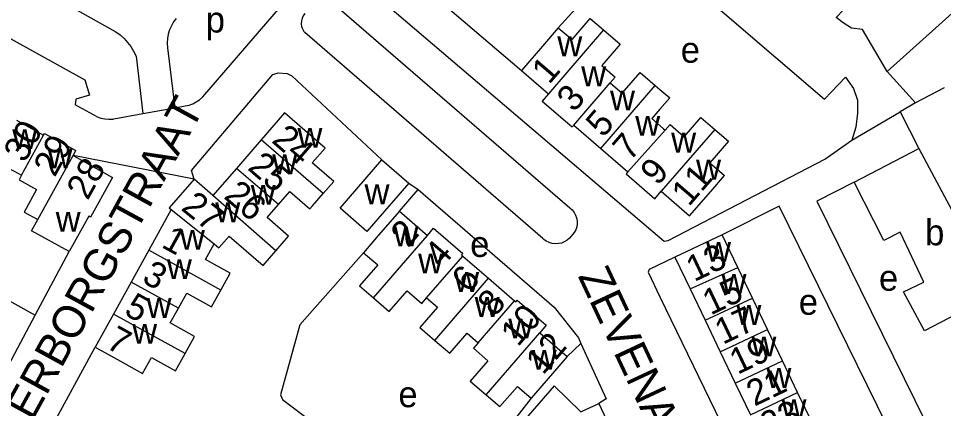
# Model space of a CAD drawing. Extents: x 158356 to 159894, y 383831 to 385260.
# Drawn here: x 159000.7 to 159143.9, y 384024.6 to 384085.1 of the extents above; entities that cross this region are included whole.
import ezdxf

# ---------------------------------------------------------------- set-up
doc = ezdxf.new("R2010")
doc.units = 0
for name, color, linetype in [('BLT_Basislijn', 7, 'Continuous'), ('BLT_Bebouwing', 7, 'Continuous'), ('BLT_Centroide', 7, 'Continuous'), ('BLT_Huisnummer', 7, 'Continuous'), ('BLT_Huisnummer_ tussenligend', 7, 'Continuous'), ('BLT_Onderverdeling_panden', 7, 'Continuous'), ('BLT_Straatnaam', 7, 'Continuous'), ('BLT_Vlakafsluiter', 7, 'Continuous')]:
    doc.layers.add(name, color=color, linetype=linetype)

msp = doc.modelspace()

# ---------------------------------------------------------------- linework, layer by layer
at = {"layer": 'BLT_Basislijn'}
for p, q in [((158953.11, 384118.31), (159015.76, 384083.03)), ((159084.24, 384083.64), (159096.05, 384096.73)), ((159049.22, 384087.62), (159086.05, 384055.72)), ((159029.22, 384072.94), (159041.26, 384086.88)), ((159067.13, 384086.81), (159078.55, 384077.03)), ((159081.89, 384050.97), (159045.03, 384082.9)), ((159023.77, 384080.55), (159024.88, 384071.25)), ((159018.89, 384079.24), (159019.95, 384070.35)), ((159012.87, 384069.86), (159009.45, 384071.71)), ((159139.58, 384072.02), (159137.17, 384070.6)), ((159015.45, 384069.52), (159019.95, 384070.35)), ((159019.95, 384070.35), (159024.88, 384071.25)), ((159024.88, 384071.25), (159026.5, 384071.54)), ((159129.68, 384066.25), (159137.17, 384070.6)), ((159137.17, 384070.6), (159140.09, 384064.94)), ((159061.1, 384059.58), (159062.57, 384058.61)), ((159059.66, 384055.21), (159062.57, 384058.61)), ((159086.53, 384051.68), (159085.98, 384051.03)), ((159003.29, 384039.1), (159008.56, 384048.99)), ((158991.32, 384045.7), (159003.29, 384039.1)), ((158996.15, 384025.71), (159003.29, 384039.1)), ((159087.75, 384034.74), (159085.65, 384032.72)), ((159005.27, 384020.8), (159012.56, 384034.13)), ((159080.04, 384026.23), (159070.07, 384013.46))]:
    msp.add_line(p, q, dxfattribs=at)
for points in [[(159069.13, 384107.67), (159068.01, 384107.77), (159066.54, 384106.24), (159054, 384091.81), (159053.62, 384090.73), (159100, 384051.15), (159100.67, 384050.58), (159101.28, 384050.68)], [(158971.07, 384097.59), (158986.45, 384089.14), (158987.15, 384086.76), (158985, 384086.14), (158984.88, 384085.24), (158989.31, 384082.78), (158990.81, 384082.66), (158995.65, 384084.07), (159010.99, 384075.6), (159011.7, 384073.19), (159009.56, 384072.58), (159009.45, 384071.71)], [(159102.52, 384092.35), (159125.48, 384072.6), (159128.71, 384076), (159129.94, 384074.26), (159130.56, 384072.41), (159130.56, 384070.43), (159130.33, 384068.23), (159129.68, 384066.25)], [(159135.19, 384076.87), (159131.34, 384083.38), (159129.67, 384083.6), (159128.37, 384084.4), (159127.3, 384085.24), (159130.84, 384089.01)], [(159025.12, 384085.11), (159024.71, 384084.55), (159024.37, 384083.95), (159024.09, 384083.31), (159023.89, 384082.65), (159023.77, 384081.97), (159023.73, 384081.28), (159023.77, 384080.55)], [(159045.02, 384085.86), (159044.77, 384085.51), (159044.6, 384085.13), (159044.49, 384084.72), (159044.47, 384084.29), (159044.53, 384083.87), (159044.66, 384083.47), (159044.87, 384083.1), (159045.03, 384082.9)], [(159015.76, 384083.03), (159016.42, 384082.55), (159017.03, 384082), (159017.59, 384081.39), (159018.08, 384080.74), (159018.51, 384080.04), (159018.89, 384079.24)], [(159027.88, 384060.18), (159027.5, 384061.52), (159040.06, 384076.43), (159040.88, 384076.66), (159042.3, 384076.59), (159042.99, 384076.22), (159056.95, 384063.17)], [(159026.5, 384071.54), (159027.1, 384071.67), (159027.68, 384071.87), (159028.22, 384072.15), (159028.73, 384072.49), (159029.22, 384072.94)], [(159012.87, 384069.86), (159013.45, 384069.65), (159014.06, 384069.52), (159014.68, 384069.47), (159015.31, 384069.5), (159015.45, 384069.52)], [(159101.28, 384050.68), (159125.52, 384063.28), (159129.68, 384066.25)], [(159130.07, 384059.7), (159124.27, 384056.8), (159146.23, 384012.21), (159163.28, 384020.54)], [(159062.57, 384058.61), (159083.6, 384040.35), (159087.4, 384035.6), (159087.75, 384034.74)], [(159131.86, 384005.09), (159141.23, 384009.67), (159118.45, 384056), (159109.62, 384051.58)], [(159086.05, 384055.72), (159086.41, 384055.41), (159086.71, 384055.04), (159086.94, 384054.63), (159087.1, 384054.19), (159087.18, 384053.73), (159087.18, 384053.26), (159087.11, 384052.79), (159086.95, 384052.35), (159086.73, 384051.94), (159086.53, 384051.68)], [(159085.98, 384051.03), (159085.61, 384050.71), (159085.19, 384050.47), (159084.74, 384050.29), (159084.27, 384050.19), (159083.78, 384050.17), (159083.3, 384050.23), (159082.84, 384050.37), (159082.4, 384050.58), (159082.01, 384050.86), (159081.89, 384050.97)], [(159054.11, 384048.78), (159044.27, 384037.62), (159041.24, 384026.76), (159041.56, 384026.03), (159046.04, 384022.62), (159046.67, 384022.22)], [(159102.32, 384048.1), (159098.34, 384046.21), (159098.18, 384045.79), (159100, 384041.97), (159120.53, 383999.56)], [(159087.75, 384034.74), (159091.65, 384026.12), (159090.52, 384025.43)]]:
    msp.add_lwpolyline(points, dxfattribs=at)
at = {"layer": 'BLT_Bebouwing'}
for p, q in [((159078.55, 384077.03), (159082.74, 384073.42)), ((159139.58, 384072.02), (159135.19, 384076.87)), ((159143.99, 384074.36), (159139.58, 384072.02)), ((159000.38, 384069.33), (159004.58, 384067.01)), ((159086.65, 384068.58), (159090.85, 384064.95)), ((159004.58, 384067.01), (159004.73, 384067.28)), ((159004.73, 384067.28), (159009.57, 384064.61)), ((159038.24, 384066.28), (159034.43, 384061.86)), ((159009.14, 384063.83), (159009.57, 384064.61)), ((159090.85, 384064.95), (159095.05, 384061.33)), ((159130.07, 384059.7), (159140.09, 384064.94)), ((159140.09, 384064.94), (159152.02, 384042.49)), ((159056.95, 384063.17), (159061.1, 384059.58)), ((159034.43, 384061.86), (159030.79, 384057.66)), ((159030.79, 384057.66), (159027.88, 384060.18)), ((159100.18, 384058.31), (159104.59, 384054.51)), ((159024.34, 384055.49), (159020.85, 384049.16)), ((159059.66, 384055.21), (159064, 384051.47)), ((159109.62, 384051.58), (159102.32, 384048.1)), ((159112.04, 384046.52), (159109.62, 384051.58)), ((159020.85, 384049.16), (159018.14, 384044.24)), ((159069.47, 384048.27), (159073.46, 384044.82)), ((159102.32, 384048.1), (159104.66, 384043.2)), ((159114.33, 384041.74), (159112.04, 384046.52)), ((159073.46, 384044.82), (159077.47, 384041.35)), ((159018.14, 384044.24), (159015.4, 384039.28)), ((159104.66, 384043.2), (159107, 384038.31)), ((159116.65, 384036.88), (159114.33, 384041.74)), ((159015.4, 384039.28), (159012.56, 384034.13)), ((159107, 384038.31), (159109.33, 384033.44)), ((159081.39, 384036.39), (159085.65, 384032.72)), ((159118.98, 384032.01), (159116.65, 384036.88)), ((159109.33, 384033.44), (159111.66, 384028.56)), ((159121.31, 384027.13), (159118.98, 384032.01)), ((159111.66, 384028.56), (159113.99, 384023.68)), ((159123.64, 384022.27), (159121.31, 384027.13)), ((159087.76, 384024.14), (159090.52, 384025.43)), ((159090.52, 384025.43), (159093.2, 384019.7))]:
    msp.add_line(p, q, dxfattribs=at)
for points in [[(159135.19, 384076.87), (159146.19, 384086.78), (159149, 384083.71), (159150.86, 384085.39), (159154.01, 384084.46), (159155.32, 384085.64)], [(159084.24, 384083.64), (159086.4, 384081.83), (159089.21, 384085.09), (159091.27, 384083.31)], [(159084.24, 384083.64), (159081.81, 384080.82), (159078.55, 384077.03)], [(159091.27, 384083.31), (159093.84, 384081.09), (159091.01, 384077.8), (159093.07, 384076.02), (159092.3, 384075.12)], [(159092.3, 384075.12), (159094.15, 384073.52), (159096.94, 384076.74), (159099.28, 384074.72)], [(159099.28, 384074.72), (159100, 384074.1), (159101.51, 384072.8), (159100, 384071.06), (159098.72, 384069.58), (159100.47, 384068.06), (159100.82, 384067.77)], [(159082.74, 384073.42), (159081.77, 384072.3), (159086.41, 384068.3), (159086.65, 384068.58)], [(159047.87, 384057.96), (159049.5, 384059.85), (159046.17, 384062.73), (159048.15, 384065.01), (159041.85, 384070.45), (159038.24, 384066.28)], [(159100.82, 384067.77), (159101.57, 384068.65), (159103.74, 384066.77), (159106.32, 384069.76), (159108.47, 384067.91)], [(159108.47, 384067.91), (159110.59, 384066.08), (159107.72, 384062.74), (159110, 384060.78)], [(159009.14, 384063.83), (159015.25, 384060.46), (159011.86, 384054.3), (159011.57, 384054.46), (159008.56, 384048.99)], [(159061.1, 384059.58), (159054.64, 384052.1), (159050.5, 384055.68), (159056.95, 384063.17)], [(158994.9, 384059.38), (158997.46, 384057.96), (158999.52, 384061.69), (159000.01, 384061.43), (159001.16, 384060.8)], [(159001.16, 384060.8), (159000.82, 384060.06), (159003.49, 384058.59), (159001.55, 384055.09), (159003.68, 384053.92)], [(159095.05, 384061.33), (159094.77, 384061), (159099.23, 384057.14), (159100.18, 384058.31)], [(159104.59, 384054.51), (159107.86, 384058.29), (159110, 384060.78)], [(159027.88, 384060.18), (159024.03, 384055.73), (159024.34, 384055.49)], [(159152.02, 384042.49), (159140.94, 384036.66), (159137.71, 384042.74), (159140.84, 384044.23), (159137.16, 384051.97), (159134.68, 384050.7), (159130.07, 384059.7)], [(159040.93, 384056.24), (159042.69, 384058.28), (159045.81, 384055.58), (159046.23, 384056.07), (159047.87, 384057.96)], [(159040.52, 384049.09), (159042.48, 384051.36), (159039.18, 384054.22), (159040.93, 384056.24)], [(159059.66, 384055.21), (159056.39, 384051.43), (159054.11, 384048.78)], [(159008.56, 384048.99), (159002.73, 384052.2), (159003.68, 384053.92)], [(159064, 384051.47), (159064.96, 384052.59), (159069.48, 384048.69), (159069.27, 384048.44), (159069.47, 384048.27)], [(159030.99, 384050.14), (159031.7, 384049.52), (159033.3, 384051.36), (159038.55, 384046.82), (159040.52, 384049.09)], [(159032.03, 384043), (159033.47, 384045.61), (159029.63, 384047.72), (159030.99, 384050.14)], [(159054.11, 384048.78), (159056.3, 384046.89), (159053.51, 384043.66), (159055.65, 384041.81)], [(159025.45, 384040.21), (159026.73, 384042.52), (159030.59, 384040.39), (159032.03, 384043)], [(159055.65, 384041.81), (159058.1, 384039.7), (159060.84, 384042.87), (159063.11, 384040.91), (159063.88, 384041.8)], [(159063.88, 384041.8), (159065.56, 384040.34), (159062.84, 384037.19), (159065.14, 384035.19)], [(159026.49, 384033.16), (159027.96, 384035.81), (159024.18, 384037.9), (159025.45, 384040.21)], [(159077.47, 384041.35), (159077.67, 384041.18), (159077.88, 384041.42), (159082.38, 384037.54), (159081.39, 384036.39)], [(159065.14, 384035.19), (159067.45, 384033.2), (159070.14, 384036.32), (159071.85, 384034.84)], [(159071.85, 384034.84), (159071.11, 384033.98), (159073.35, 384032.04), (159070.64, 384028.89), (159073.09, 384026.78)], [(159012.56, 384034.13), (159016.93, 384031.71), (159019.9, 384030.08), (159021.27, 384032.57), (159025.02, 384030.5), (159026.49, 384033.16)], [(159085.65, 384032.72), (159082.38, 384028.93), (159080.04, 384026.23)], [(159073.09, 384026.78), (159075.22, 384024.93), (159077.92, 384028.06), (159080.04, 384026.23)], [(159087.76, 384024.14), (159083.63, 384028.13), (159077.84, 384021.48), (159078.75, 384019.53), (159080.44, 384020.31)]]:
    msp.add_lwpolyline(points, dxfattribs=at)
at = {"layer": 'BLT_Onderverdeling_panden'}
for p, q in [((159091.27, 384083.31), (159082.74, 384073.42)), ((159086.65, 384068.58), (159092.3, 384075.12)), ((159090.85, 384064.95), (159099.28, 384074.72)), ((159095.05, 384061.33), (159100.82, 384067.77)), ((159108.47, 384067.91), (159100.18, 384058.31)), ((159001.16, 384060.8), (159004.58, 384067.01)), ((159047.87, 384057.96), (159038.24, 384066.28)), ((159003.68, 384053.92), (159009.14, 384063.83)), ((159040.93, 384056.24), (159034.43, 384061.86)), ((159040.52, 384049.09), (159030.79, 384057.66)), ((159024.34, 384055.49), (159030.99, 384050.14)), ((159055.65, 384041.81), (159064, 384051.47)), ((159032.03, 384043), (159020.85, 384049.16)), ((159063.88, 384041.8), (159069.47, 384048.27)), ((159104.66, 384043.2), (159112.04, 384046.52)), ((159065.14, 384035.19), (159073.46, 384044.82)), ((159025.45, 384040.21), (159018.14, 384044.24)), ((159107, 384038.31), (159114.33, 384041.74)), ((159071.85, 384034.84), (159077.47, 384041.35)), ((159026.49, 384033.16), (159015.4, 384039.28)), ((159073.09, 384026.78), (159081.39, 384036.39))]:
    msp.add_line(p, q, dxfattribs=at)
for points in [[(159109.33, 384033.44), (159116.65, 384036.88)], [(159111.66, 384028.56), (159118.98, 384032.01)], [(159113.99, 384023.68), (159121.31, 384027.13)]]:
    msp.add_lwpolyline(points, dxfattribs=at)
at = {"layer": 'BLT_Vlakafsluiter'}
msp.add_line((159027.88, 384060.18), (159009.14, 384063.83), dxfattribs=at)

# ---------------------------------------------------------------- texts
at = {"layer": 'BLT_Centroide'}
for s, p in [('p', (159029.68, 384082.92)), ('w', (159084.11, 384079.25)), ('e', (159103.22, 384078.24)), ('w', (159087.81, 384074.59)), ('w', (159092.27, 384070.84)), ('w', (159096.17, 384066.91)), ('w', (158999.73, 384064.86)), ('w', (159043.88, 384065.06)), ('w', (159101.73, 384064.3)), ('w', (159005.2, 384061.86)), ('w', (159039.98, 384060.94)), ('w', (159105.59, 384060.12)), ('w', (159036.64, 384056.23)), ('w', (159054.27, 384056.3)), ('w', (159031.16, 384053.5)), ('w', (159006.45, 384052.05)), ('b', (159141.05, 384049.94)), ('w', (159025.69, 384049.25)), ('w', (159058.75, 384049.78)), ('e', (159070.62, 384048.13)), ('w', (159107.14, 384047.38)), ('w', (159023.67, 384044.69)), ('w', (159062.56, 384045.59)), ('e', (159133.9, 384042.89)), ('w', (159068.14, 384042.72)), ('w', (159109.52, 384042.41)), ('w', (159020.53, 384038.69)), ('w', (159071.31, 384038.83)), ('e', (159121.49, 384039.17)), ('w', (159111.83, 384037.59)), ('w', (159018.3, 384034.69)), ('w', (159076.52, 384035.5)), ('w', (159114.16, 384032.72)), ('w', (159080.16, 384030.66)), ('w', (159116.48, 384027.84)), ('e', (159059.51, 384024.84)), ('w', (159118.81, 384022.97))]:
    msp.add_text(s, height=4, dxfattribs=at).set_placement(p)
at = {"layer": 'BLT_Huisnummer'}
for s, rotation, p in [('1', 49.2082, (159082.83, 384074.75)), ('5', 49.2082, (159091.2, 384066.49)), ('24', 319.1579, (159039.73, 384066.01)), ('28', 61.1417, (159011.41, 384056.78)), ('11', 49.2082, (159104.47, 384055.81)), ('26', 319.1579, (159032.32, 384057.35)), ('2', 49.179, (159060.98, 384049.45)), ('1', 331.1159, (159022.65, 384049.73)), ('13', 25.4917, (159105.29, 384044.21)), ('6', 49.179, (159070.42, 384042.39)), ('17', 25.4917, (159109.73, 384034.48)), ('7', 331.0572, (159014.04, 384034.15)), ('12', 49.1849, (159081.89, 384029.71)), ('21', 25.4917, (159114.61, 384024.91))]:
    msp.add_text(s, height=4, rotation=rotation, dxfattribs=at).set_placement(p)
at = {"layer": 'BLT_Huisnummer_ tussenligend'}
for s, rotation, p in [('3', 49.2082, (159086.7, 384070.42)), ('30', 61.1417, (159001.67, 384062.58)), ('7', 49.2082, (159095.35, 384062.84)), ('29', 61.1417, (159006.3, 384060.36)), ('25', 319.1579, (159036.01, 384061.78)), ('9', 49.2082, (159099.64, 384059.03)), ('27', 321.1627, (159025.7, 384055.52)), ('4', 49.179, (159066.19, 384046.27)), ('3', 331.1159, (159019.62, 384044.32)), ('15', 25.4917, (159107.83, 384039.03)), ('5', 331.1159, (159016.86, 384039.28)), ('8', 49.179, (159074.41, 384038.7)), ('10', 49.179, (159078.01, 384034.08)), ('19', 25.4917, (159112.01, 384029.84)), ('23', 25.4917, (159116.75, 384019.99))]:
    msp.add_text(s, height=4, rotation=rotation, dxfattribs=at).set_placement(p)
at = {"layer": 'BLT_Straatnaam'}
for s, rotation, p in [('1E TERBORGSTRAAT', 61.2486, (158996.06, 384010.21)), ('ZEVENAARLAAN', 295.0902, (159087.24, 384045.18))]:
    msp.add_text(s, height=5, rotation=rotation, dxfattribs=at).set_placement(p)

doc.saveas('drawing.dxf')
